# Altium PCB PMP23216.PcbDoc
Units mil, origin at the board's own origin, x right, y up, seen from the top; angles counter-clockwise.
Board outline 1612.03 x 1092.87 mil, 4 copper layers (Top Layer, Signal Layer 1, Signal Layer 2, Bottom Layer), stack 36.024 mil thick; 28 components, 16 nets, 71 pads, 14 vias.
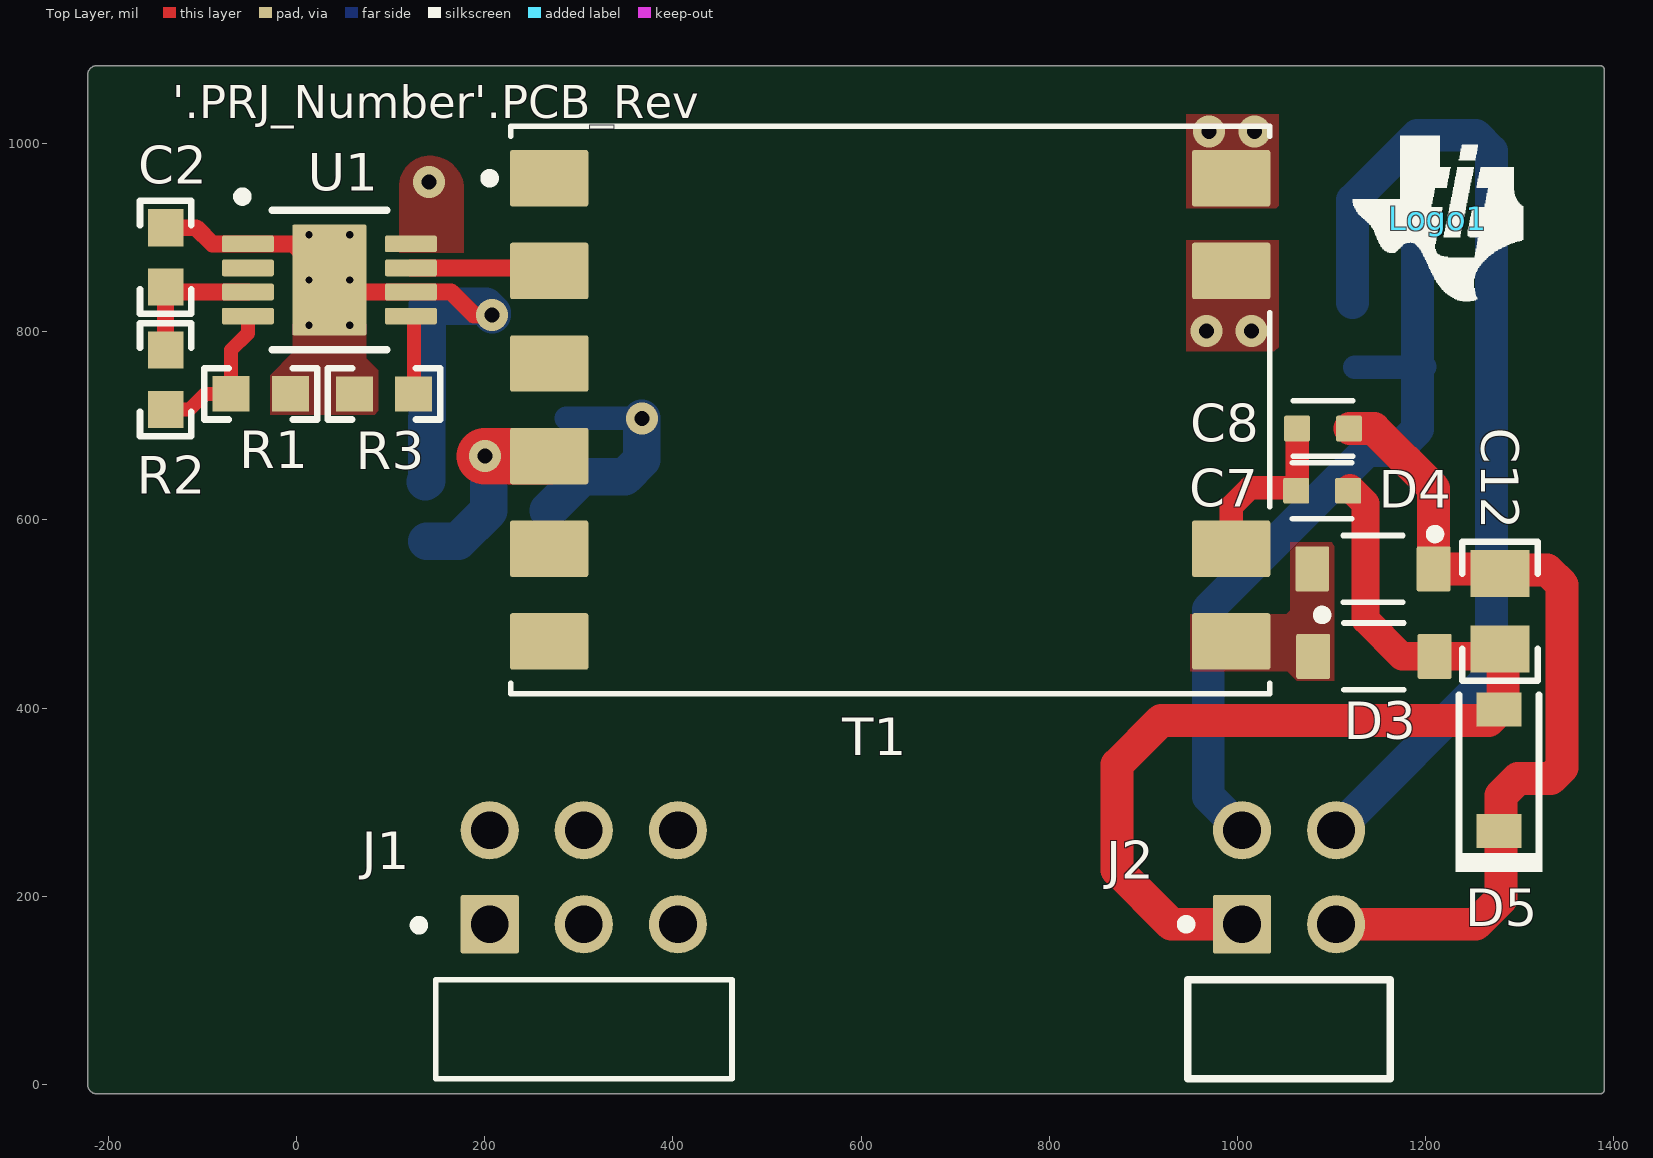
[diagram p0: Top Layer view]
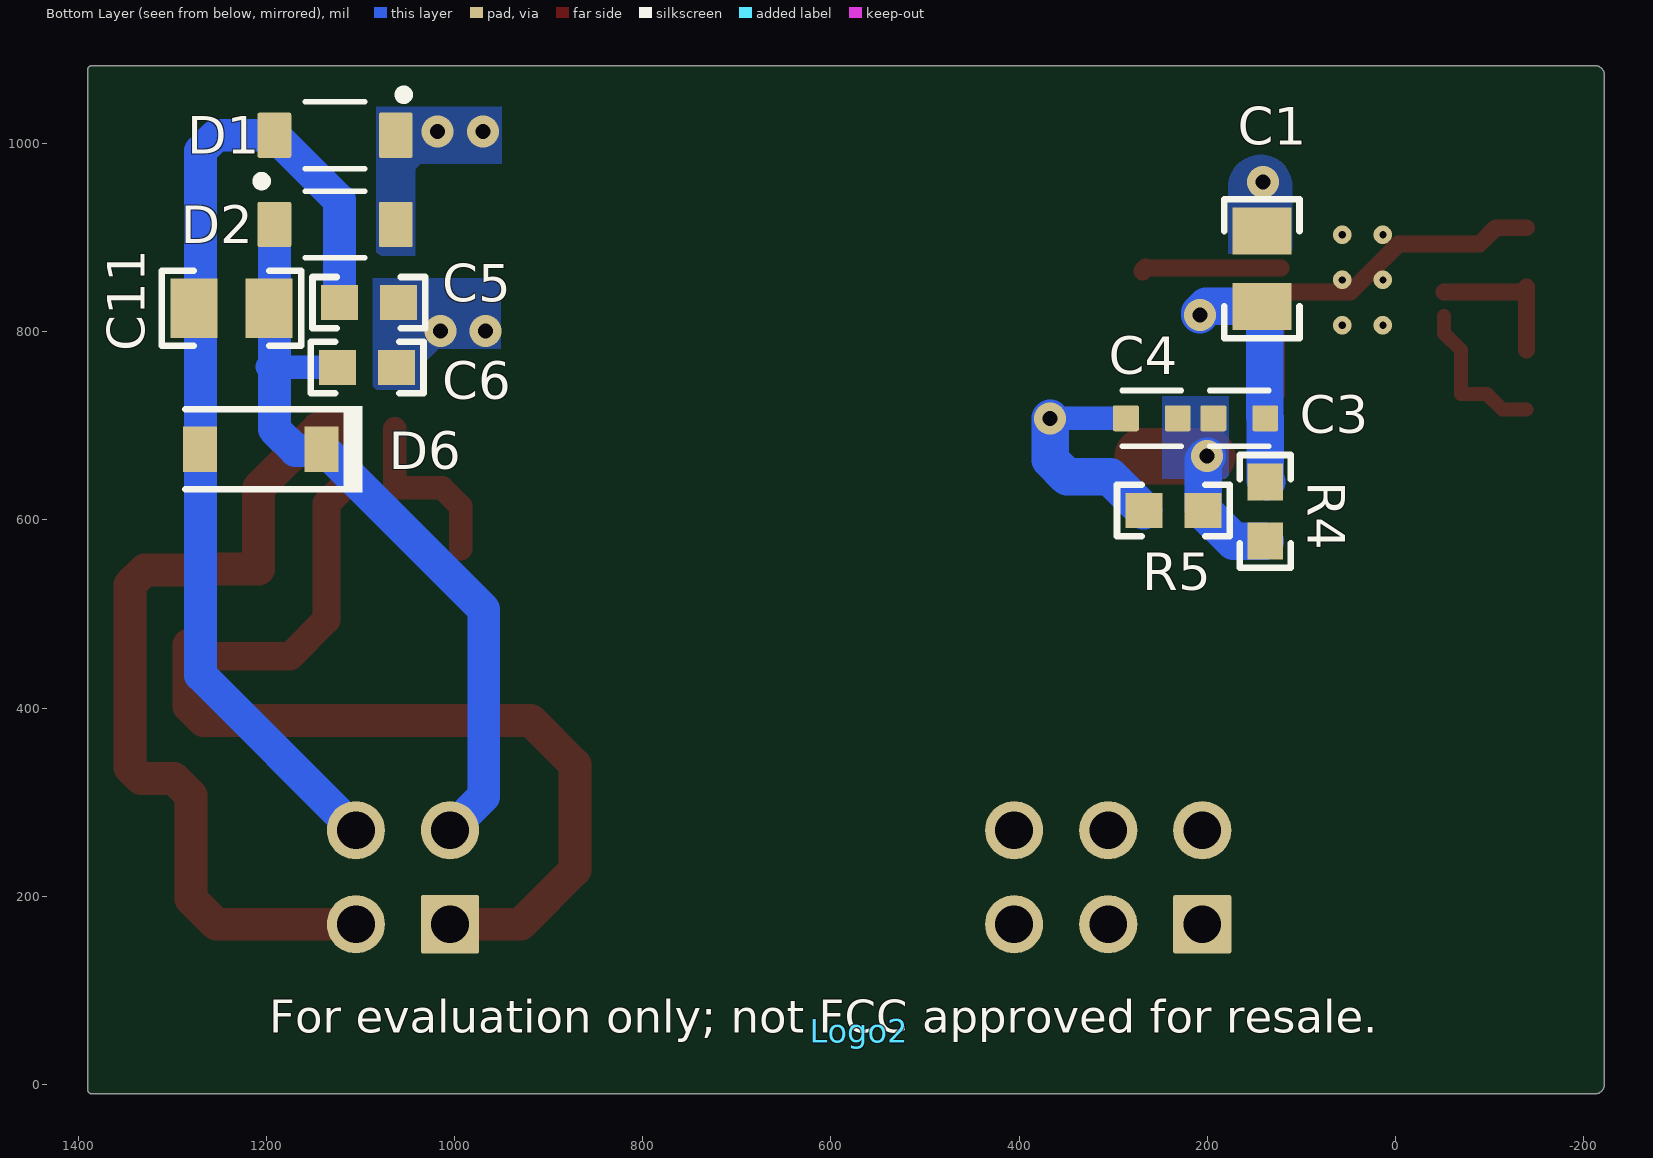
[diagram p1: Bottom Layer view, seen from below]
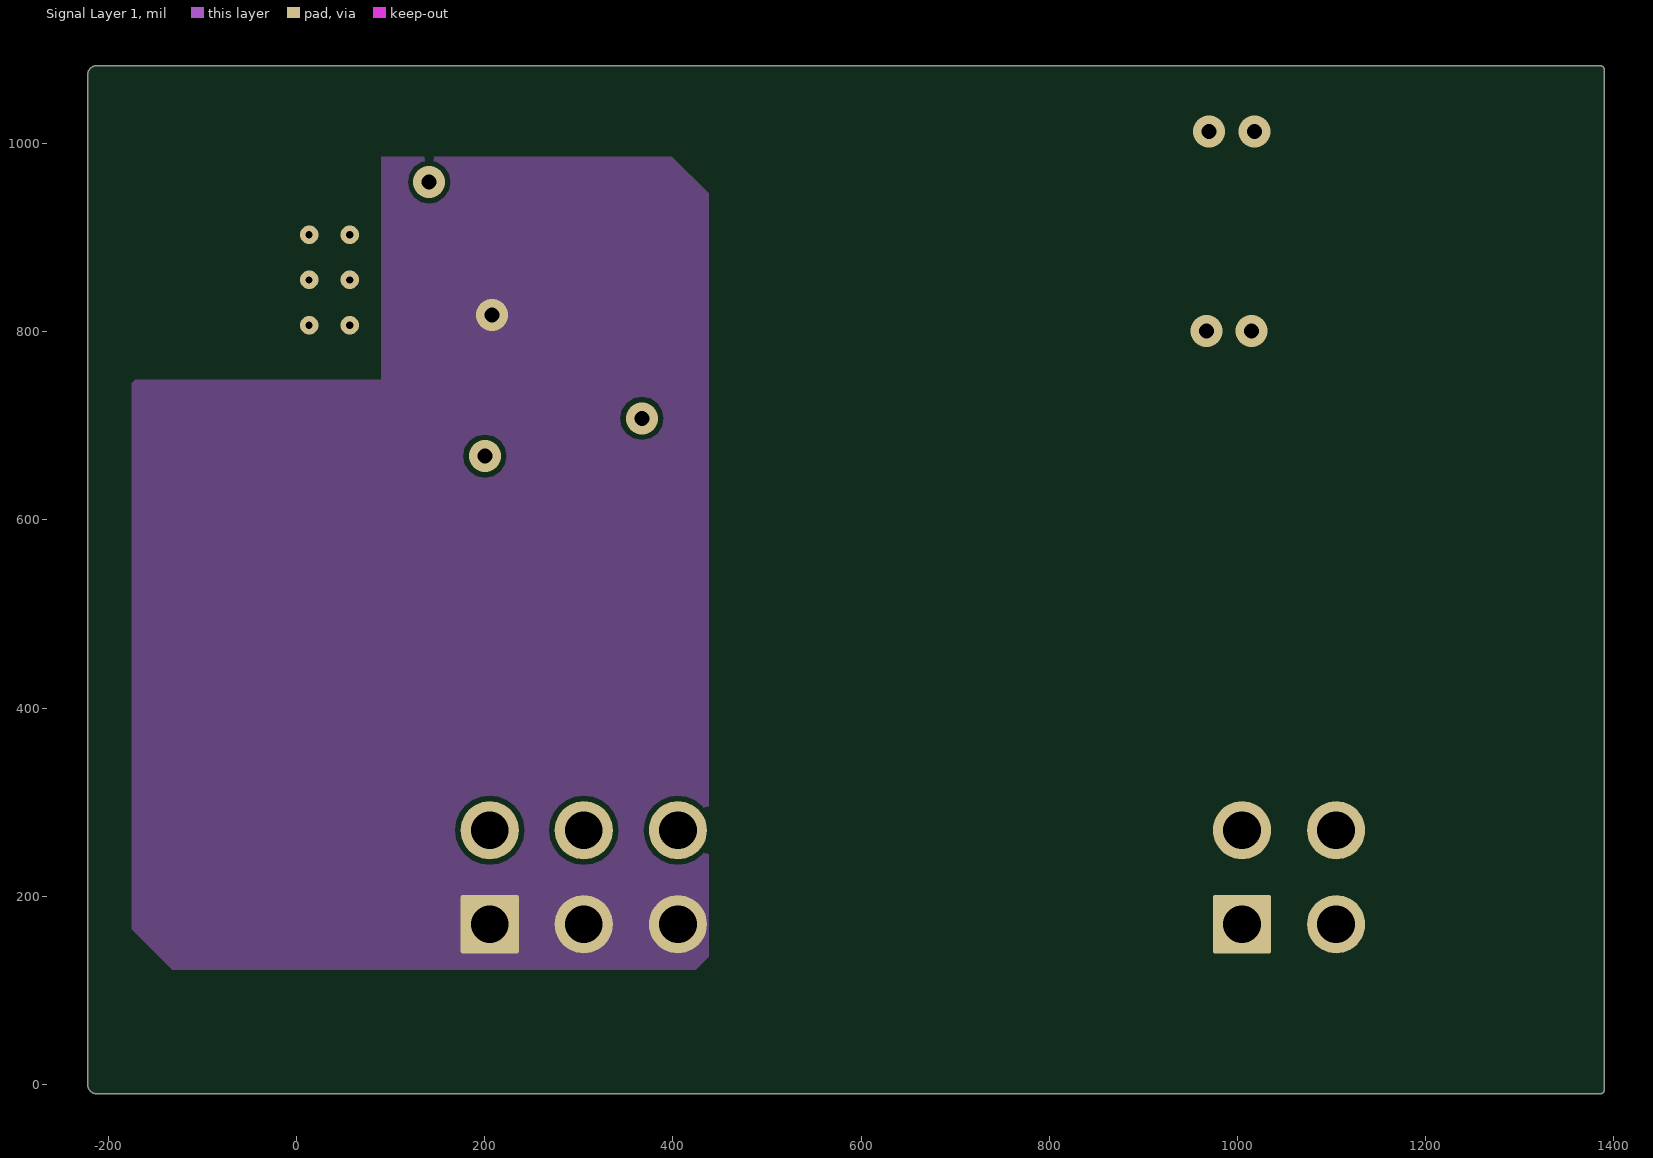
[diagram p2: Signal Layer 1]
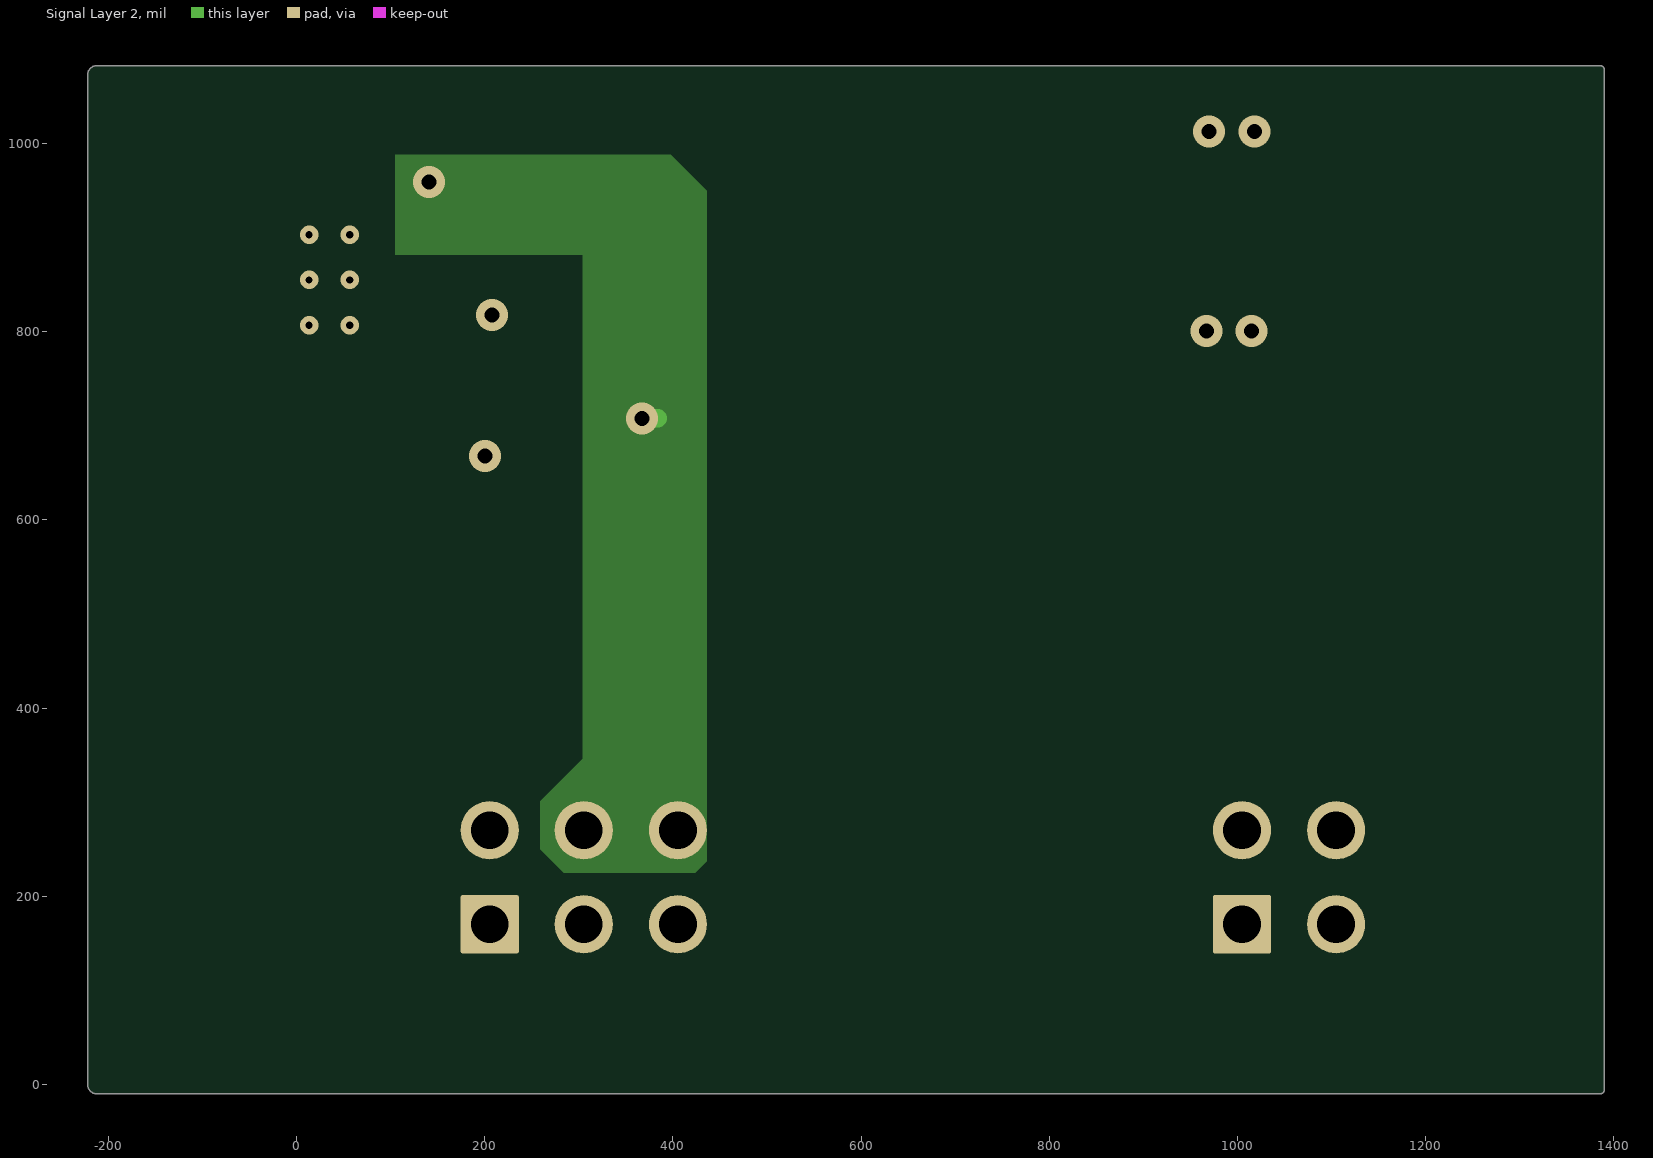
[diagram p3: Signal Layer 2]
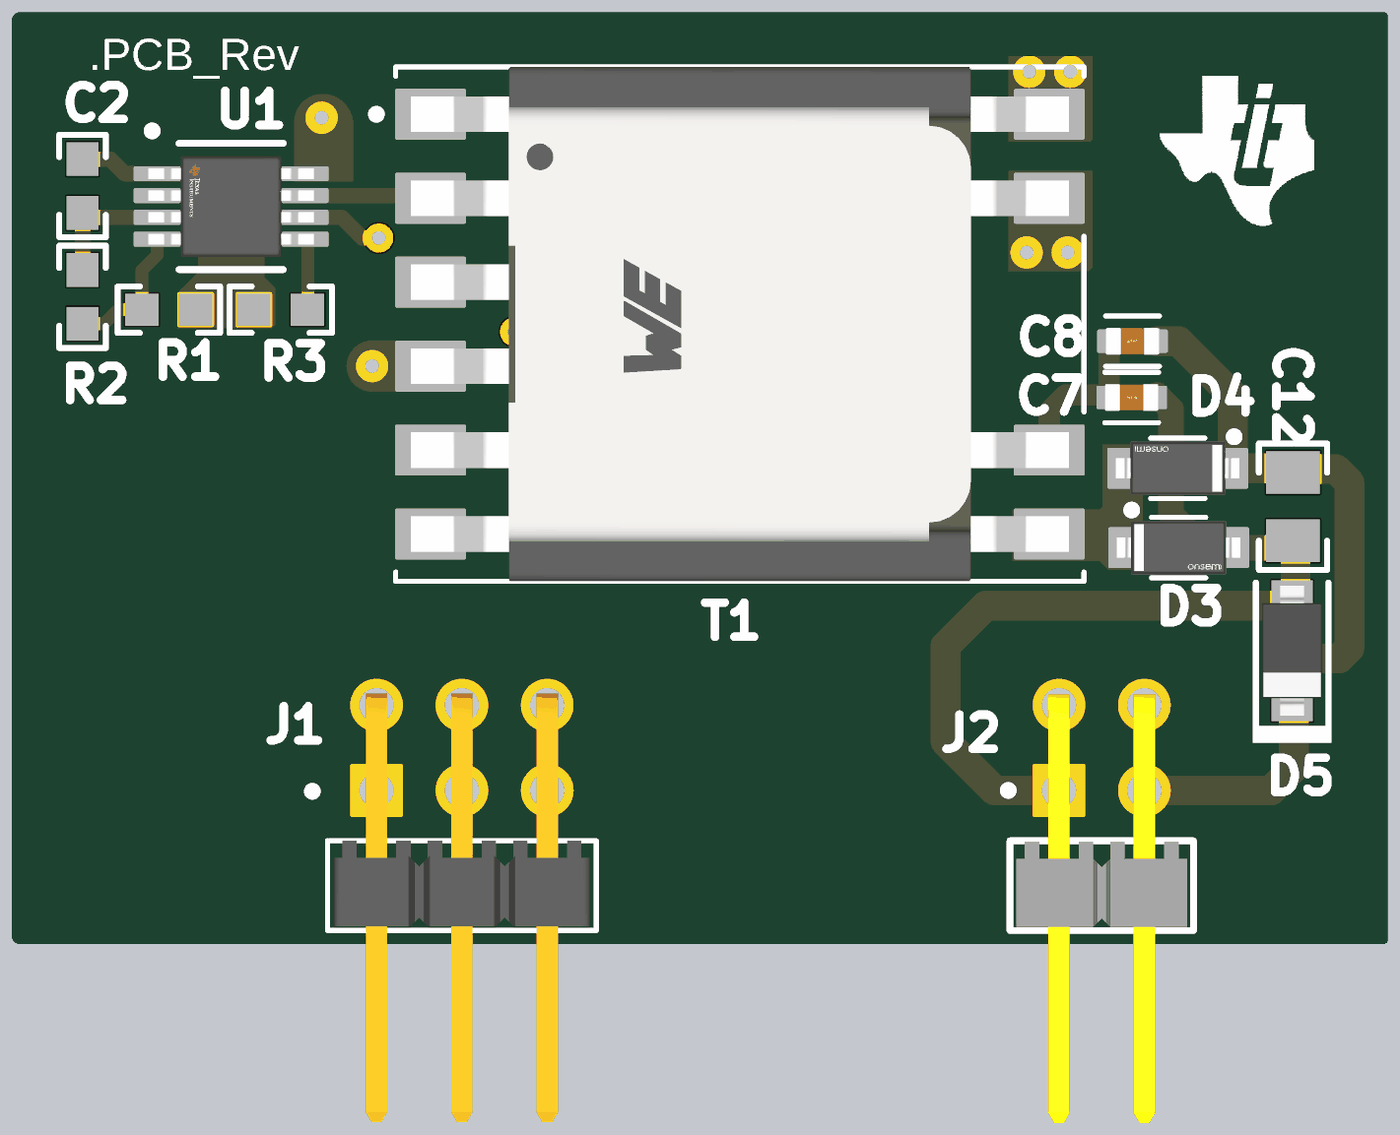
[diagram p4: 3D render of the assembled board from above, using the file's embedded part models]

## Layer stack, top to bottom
Top Solder: solder mask 0.4, Solder Resist, Dk 3.5
Top Layer: signal copper 2.756
Dielectric 2: core 10, FR-4, Dk 4.2
Signal Layer 1: signal copper 2.756
Dielectric1: prepreg 5, FR-4, Dk 4.2
Signal Layer 2: signal copper 2.756
Dielectric 3: core 10, FR-4, Dk 4.2
Bottom Layer: signal copper 2.756
Bottom Solder: solder mask 0.4, Solder Resist, Dk 3.5

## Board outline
-212,-10.02 cw(c-212,0) -222.02,0 -222.02,1072.83 cw(c-212,1072.83) -212,1082.85 1385,1082.85 cw(c1385,1077.84) 1390.01,1077.84 1390.01,-5 cw(c1385,-5) 1385,-10.02

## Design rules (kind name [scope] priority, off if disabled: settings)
AcuteAngle [All] p1: minimum=4.50000000000000E+0001 checktracksonly=FALSE
AssemblyTestPointUsage [All] p1: valid=2
BoardOutlineClearance BoardOutlineClearance_MountingHoles [OnCopper and InComponentClass('Mounting Holes')] p1: gap=39.37 ignorepadtopadclearanceinfootprint=FALSE
BoardOutlineClearance BoardOutlineClearance_Poly [OnCopper and IsPoly] p2: gap=25 ignorepadtopadclearanceinfootprint=FALSE
BoardOutlineClearance [OnCopper and Not InComponentClass('Logo') and not InComponentClass('FiducialMark') and not InRegion(1000,500,4000,800) and not InPoly] p3: gap=25 ignorepadtopadclearanceinfootprint=FALSE
Clearance Clearance_SW_PGND [InNetClass('VSWNET') vs InNetClass('PGND')] p1: gap=50 ignorepadtopadclearanceinfootprint=TRUE
Clearance Clearance_Keepouts [((IsTrack Or IsArc) And Not InPoly) And IsFree and IsKeepOut vs ((IsTrack Or IsArc) And Not InPoly) And IsFree and IsKeepOut] p2: gap=0 ignorepadtopadclearanceinfootprint=FALSE
Clearance Clearance_Poly [InPolygon] p3: gap=5.5 ignorepadtopadclearanceinfootprint=TRUE
Clearance Clearance_FiducialMark [IsKeepOut and InComponentClass('FiducialMark') vs IsPad and InComponentClass('FiducialMark')] p4: gap=0 ignorepadtopadclearanceinfootprint=FALSE
Clearance [All] p5: gap=7 ignorepadtopadclearanceinfootprint=TRUE
ComponentClearance ComponentClearance_MountingHoles_FiducialMarks [InComponentClass('Mounting Holes') vs InComponentClass('FiducialMark')] p1: gap=50 collisioncheckmode=3 verticalgap=10 showdistances=FALSE
ComponentClearance ComponentClearance_Shunt [InComponentClass('Header') vs InComponentClass('Shunt')] p2: gap=0 collisioncheckmode=3 verticalgap=0 showdistances=FALSE
ComponentClearance ComponentClearance_Logo [InComponentClass('Logo')] p3: gap=50 collisioncheckmode=3 verticalgap=10 showdistances=FALSE
ComponentClearance ComponentClearance_ScrewToNut [(HasFootprint('NY PMS 440 0025 PH')) vs (HasFootprint('Keystone_1902C'))] p4: gap=5 collisioncheckmode=3 verticalgap=10 showdistances=FALSE
ComponentClearance ComponentClearance_MountingHoles [InComponentClass('Mounting Holes')] p5: gap=250 collisioncheckmode=3 verticalgap=100000 showdistances=FALSE
ComponentClearance ComponentClearance_SmallPassives [HasFootprint('0201*') or HasFootprint('0402*') or HasFootprint('0508') or HasFootprint('0603*') or HasFootprint('0612') or HasFootprint('0805*') or HasFootprint('0815*') or HasFootprint('0830*') or HasFootprint('1206*') or HasFootprint('1210*') or HasFootprint('1808*') or HasFootprint('1812*') or HasFootprint('1825*') or HasFootprint('2010*') or HasFootprint('2220*') or HasFootprint('2225*') or HasFootprint('2512*') or HasFootprint('2728*') or HasFootprint('3518*') vs HasFootprint('0201*') or HasFootprint('0402*') or HasFootprint('0508') or HasFootprint('0603*') or HasFootprint('0612') or HasFootprint('0805*') or HasFootprint('0815*') or HasFootprint('0830*') or HasFootprint('1206*') or HasFootprint('1210*') or HasFootprint('1808*') or HasFootprint('1812*') or HasFootprint('1825*') or HasFootprint('2010*') or HasFootprint('2220*') or HasFootprint('2225*') or HasFootprint('2512*') or HasFootprint('2728*') or HasFootprint('3518*')] p6: gap=14.96 collisioncheckmode=3 verticalgap=10 showdistances=FALSE
ComponentClearance ComponentClearance_THtoSMT [IsThruComponent vs IsSMTComponent] p7: gap=40 collisioncheckmode=3 verticalgap=30 showdistances=FALSE
ComponentClearance ComponentClearance_THtoTH [IsThruComponent vs IsThruComponent] p8: gap=30 collisioncheckmode=3 verticalgap=30 showdistances=FALSE
ComponentClearance [All] p9: gap=30 collisioncheckmode=3 verticalgap=10 showdistances=FALSE
DiffPairsRouting [All] p1: maxlimit=100 minlimit=10 mostfreqgap=10 toplayer_minwidth=15 toplayer_maxwidth=15 toplayer_prefwidth=15 midlayer1_minwidth=15 midlayer1_maxwidth=15 midlayer1_prefwidth=15 midlayer2_minwidth=15 midlayer2_maxwidth=15 midlayer2_prefwidth=15 bottomlayer_minwidth=15 bottomlayer_maxwidth=15 bottomlayer_prefwidth=15 maxuncoupledlength=1000
FabricationTestPointUsage TestPointUsage [All] p1: valid=2 allowmultiple=FALSE
FabricationTestpoint Testpoint [All] p1: side=3 testpointundercomponent=TRUE minsize=40 maxsize=100 preferedsize=60 minholesize=0 maxholesize=40 preferedholesize=32 testpointgrid=1 allowsidetop=TRUE allowsidebottom=TRUE usegrid=TRUE gridtolerance=0.01
FanoutControl Fanout_LCC [IsLCC] p1: bgadir=Out bgaviamode=Centered fanoutstyle=Auto fanoutdirection=Alternating viagrid=1 // Fanout_LCC (Default Rule)
FanoutControl Fanout_BGA [IsBGA] p2: bgadir=Out bgaviamode=Centered fanoutstyle=Auto fanoutdirection=Alternating viagrid=1 // Fanout_BGA (Default Rule)
FanoutControl Fanout_Default [All] p4: bgadir=Out bgaviamode=Centered fanoutstyle=Auto fanoutdirection=Alternating viagrid=1 // Fanout_Default (Default Rule)
FanoutControl Fanout_Small [(CompPinCount < 5)] p5: bgadir=Out bgaviamode=Centered fanoutstyle=Auto fanoutdirection=OutThenIn viagrid=1 // Fanout_Small (Default Rule)
HoleSize [All] p1: absolutevalues=TRUE maxlimit=251 minlimit=7.87 maxpercent=80.000 minpercent=20.000
MinimumAnnularRing MinimumAnnularRing_ThermalPadVias [IsVia and InAnyComponent] p1: minimumring=5.91
MinimumAnnularRing [All] p2: minimumring=7.87
MinimumSolderMaskSliver MinimumSolderMaskSliver_Logo [InComponentClass('Logo') vs InComponentClass('Logo')] p1: minsoldermaskwidth=0.7
MinimumSolderMaskSliver [All] p2: minsoldermaskwidth=3.94
PlaneConnect [All] p1: planeconnectstyle=Direct reliefexpansion=10 reliefentries=4 reliefconductorwidth=10 reliefairgap=10
PolygonConnect [All] p1: connectstyle=Direct reliefconductorwidth=10 reliefentries=4 polygonreliefangle="90 Angle" airgapwidth=10
RoutingVias ThermalPadVias [IsVia and InAnyComponent] p1: holewidth=7.87 width=19.68 viastyle="Through Hole" minholewidth=7.87 minwidth=19.68 maxholewidth=12.99 maxwidth=23.62
RoutingVias [All] p2: holewidth=16 width=34 viastyle="Through Hole" minholewidth=7.87 minwidth=26 maxholewidth=40 maxwidth=65
SilkToBoardRegionClearance [Not ((IsComment or IsDesignator) And (Hide <> 'False')) and not InRegion(1000,500,4000,800)] p1:
SilkToSilkClearance SilkToSilkClearance_Pb-FreeLogo [(HasFootprint('Pb-Free_Overlay_Medium') OR HasFootprint('Pb-Free_Overlay_Small')) vs (HasFootprint('Pb-Free_Overlay_Medium') OR HasFootprint('Pb-Free_Overlay_Small'))] p1: silktosilkclearance=0
SilkToSilkClearance [All] p2: silktosilkclearance=3.94
SilkToSolderMaskClearance SilkToComponentPadClearance [(IsPad or IsFill or IsRegion) and InAnycomponent] p1: minsilkscreentomaskgap=5 clearancetoexposedcopper=TRUE
SilkToSolderMaskClearance "Silk to Solder Mask Opening" [All] p2: minsilkscreentomaskgap=3.94 clearancetoexposedcopper=FALSE
SolderMaskExpansion [All] p1: expansion=1.97
UnRoutedNet [All] p1: checkbadconnections=TRUE
Width [All] p1: maxlimit=100 minlimit=6 preferedwidth=10 checkconnectedcopper=TRUE
14 further rules are at their usual default settings.

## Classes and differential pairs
net class VSWNET: H_XFMR_BOT H_XFMR_TOP HS_GND ISO_12V_H
net class PGND: ISO_12V_L L_XFMR_BOT L_XFMR_TOP LS_GND
net class INGND: 12V_PRI NetU1_2 OC_DT PGND PRI_BOT RT SW VREG
component class PMP23216_sheet1: C1 C2 C3 C4 C5 C6 C7 C8 C11 C12 D1 D2 D3 D4 D5 D6 J1 J2 R1 R2 R3 R4 R5 T1 U1
component class Logo: Logo1
component class PMP23216_Hardware: Logo1 Logo2 Logo3

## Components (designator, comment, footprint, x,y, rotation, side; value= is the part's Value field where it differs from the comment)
C1 "GRM219R61E106KA12D" 0805_HV 142,867 r270 bottom value=10uF
C2 "GRM185R61A105KE36D" 0603 -139,879 r90 top value=1uF
C3 "C1608X8R1E683M080AA" FP-C1608X8R1E683M080AA_0603-MFG 166,708 r0 bottom value=68nF
C4 "C1608X8R1E683M080AA" FP-C1608X8R1E683M080AA_0603-MFG 259,708 r0 bottom value=68nF
C5 "GRM188R61E475KE11D" 0603 1091,831 r0 bottom value=4.7uF
C6 "GRM188R61E475KE11D" 0603 1093,762 r180 bottom value=4.7uF
C7 "C1608X5R1E475M080AC" FP-C1608X5R1E475M080AC_0603-MFG 1090,631 r180 top value=4.7µF
C8 "C1608X5R1E475M080AC" FP-C1608X5R1E475M080AC_0603-MFG 1091,697 r0 top value=4.7µF
C11 "GRM21BR71E475KA73L" 0805_HV 1237,825 r0 bottom value=4.7uF
C12 "GRM21BR71E475KA73L" 0805_HV 1279,503 r270 top value=4.7uF
D1 "MBR130T3G" FP-MBR130T3G_SOD123-MFG 1127,1008.81 r0 bottom
D2 "MBR130T3G" FP-MBR130T3G_SOD123-MFG 1127,914 r180 bottom
D3 "MBR130T3G" FP-MBR130T3G_SOD123-MFG 1145,455 r0 top
D4 "MBR130T3G" FP-MBR130T3G_SOD123-MFG 1144,548 r180 top
D5 "MMSZ4702T1G" SOD-123 1278,334 r90 top value=15V
D6 "MMSZ4702T1G" SOD-123 1206,675 r0 bottom value=15V
J1 "TSW-103-08-G-D-RA" FP-TSW-103-08-G-D-RA_HDR6-MFG 305.36,61.22 r0 top locked
J2 "TSW-102-08-G-D-RA" FP-TSW-102-08-G-D-RA_HDR4-MFG 1054.87,61.22 r0 top
Logo1 "Texas Instruments" TI_Symbol_Overlay_Small 1213,920 r0 top
Logo2 "FCC disclaimer" FCC_disclaimer 570,57 r180 bottom
Logo3 "WEEE logo" WEEE_Minimum 2670,490 r0 top
R1 "RT0603DRE0711K4L" 0603 -38,734 r180 top value=11.4k
R2 "RT0603BRD073K2L" 0603 -139,749 r90 top value=3.20k
R3 "RT0603DRE0750K5L" 0603 93,733.93 r0 top value=50.5k
R4 "RT0603BRD073K2L" 0603 138.44,609 r270 bottom value=3.20k
R5 "RT0603BRD073K2L" 0603 236,610 r0 bottom value=3.20k
T1 "750320012" FP-750320012_SMT_XFRMR_20MM48_15MM32-MFG 631,717 r0 top locked
U1 "UCC25800DGNRQ1" DGN0008G-MFG 35,855 r0 top

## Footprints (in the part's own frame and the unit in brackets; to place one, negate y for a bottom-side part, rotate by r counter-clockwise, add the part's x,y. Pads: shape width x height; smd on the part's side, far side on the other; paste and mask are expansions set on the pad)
0603 [mm] "0603 from SM-752 data"
  rect 1x0.95 smd: 1(-0.8,0) 2(0.8,0)
  silkscreen extent -1.52,-0.69 1.52,0.69, body extent -0.87,-0.47 0.87,0.47, height 1
0805_HV [mil] "0805 with 30mil clearance between pads"
  rect 50x63 smd: 1(-40,0) 2(40,0)
  silkscreen extent -74,-40 74,40, body extent -43,-29 43,29, height 57
DGN0008G-MFG [mm]
  rrect22% 1.4x0.45 smd paste+0 mask+0: 1(-2.2,0.975) 2(-2.2,0.325) 3(-2.2,-0.325) 4(-2.2,-0.975) 5(2.2,-0.975) 6(2.2,-0.325) 7(2.2,0.325) 8(2.2,0.975)
  rrect5% 2x3 smd paste-1000 mask-1000: 9(0,0)
  silkscreen extent -2.47,-1.88 1.55,2.37, body extent -2.46,-1.5 2.46,1.5, height 1.1
FCC_disclaimer [mil]
FP-750320012_SMT_XFRMR_20MM48_15MM32-MFG [mm]
  rrect7% 2.11x1.52 smd paste+0 mask+0: 1(-9.205,6.25) 2(-9.205,3.75) 3(-9.205,1.25) 4(-9.205,-1.25) 5(-9.205,-3.75) 6(-9.205,-6.25) 7(9.205,-6.25) 8(9.205,-3.75) 9(9.205,3.75) 10(9.205,6.25)
  silkscreen extent -10.94,-7.66 10.24,7.66, body extent -10.36,-7.76 10.36,7.76, height 0.25
FP-C1608X5R1E475M080AC_0603-MFG [mm]
  rrect14% 0.7x0.7 smd paste+0 mask+0: 1(-0.7,0) 2(0.7,0)
  silkscreen extent -0.8,-0.75 0.8,0.75, body extent -1.15,-0.55 1.15,0.55, height 0.25
FP-C1608X8R1E683M080AA_0603-MFG [mm]
  rrect14% 0.7x0.7 smd paste+0 mask+0: 1(-0.7,0) 2(0.7,0)
  silkscreen extent -0.8,-0.75 0.8,0.75, body extent -0.8,-0.4 0.8,0.4, height 0.9
FP-MBR130T3G_SOD123-MFG [mil]
  rrect11% 36x48 smd paste+0 mask+0: 1(-64.5,0) 2(64.5,0)
  silkscreen extent -78,-48 32,35, body extent -72,-31 72,31, height 53
FP-TSW-102-08-G-D-RA_HDR4-MFG [mm]
  rrect6% 1.57x1.57 hole 1.02 paste-1000 mask+0: 1(-1.27,2.77)
  round 1.57 hole 1.02 paste-1000 mask+0: 2(-1.27,5.31) 3(1.27,2.77) 4(1.27,5.31)
  silkscreen extent -2.9,-1.4 2.73,2.89, body extent -2.83,-7.54 2.83,6.2, height 0.25
FP-TSW-103-08-G-D-RA_HDR6-MFG [mm]
  rrect6% 1.57x1.57 hole 1.02 paste-1000 mask+0: 1(-2.54,2.77)
  round 1.57 hole 1.02 paste-1000 mask+0: 2(-2.54,5.31) 3(0,2.77) 4(0,5.31) 5(2.54,2.77) 6(2.54,5.31)
  silkscreen extent -4.57,-1.4 4,2.87, body extent -4.1,-7.54 4.1,6.19, height 0.25
SOD-123 [mm] "On Semi recommended land pattern"
  rect 0.915x1.22 smd: 1(-1.637,0) 2(1.637,0)
  silkscreen extent -2.74,-1.17 2.03,1.17, body extent -1.93,-0.9 1.93,0.9, height 1.35
TI_Symbol_Overlay_Small [mil]
  silkscreen extent -90,-88 91,88
WEEE_Minimum [mil] "WEEElie bin"
  silkscreen extent -95,-172 99,104

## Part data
C1: library part CMP-0008206-2, "CAP, CERM, 10 uF, 25 V, +/- 10%, X5R, 0805", Cap_Case=0805, Manufacturer=MuRata, Supplier Part Number 1=490-7207-1-ND, TempCo=X5R, Tolerance_%=10%, Value1=Unknown, Value2=25V, ValueDisplayed=10uF
C2: library part CMP-0007156-4, "CAP, CERM, 1 uF, 10 V, +/- 10%, X5R, 0603", Cap_Case=0603, Manufacturer=MuRata, Supplier Part Number 1=490-3893-1-ND, TempCo=X5R, Tolerance_%=10%, Value1=Unknown, Value2=10V, ValueDisplayed=1uF
C3 C4: library part CMP-0094554-1, "Multilayer Ceramic Capacitors 68nF ±20% 25V X8R SMD 0603", Manufacturer=TDK, Operating Temperature Range="-55°C to +150°C", TempCo=0.15, Temperature Characteristic=X8R, Tolerance_%=0.2%, ValueDisplayed=68nF, Voltage=50V
C5 C6: library part CMP-0007347-4, "CAP, CERM, 4.7 uF, 25 V, +/- 10%, X5R, 0603", Cap_Case=0603, Manufacturer=MuRata, Supplier Part Number 1=490-7203-1-ND, TempCo=X5R, Tolerance_%=10%, Value1=Unknown, Value2=25V, ValueDisplayed=1µF
C7 C8: library part CMP-0094553-1, "Multilayer Ceramic Capacitors 4.7µF ±20% 25V X5R SMD 0603", Manufacturer=TDK, Operating Temperature Range="-55°C to +85°C", TempCo=0.15, Temperature Characteristic=X5R, Tolerance_%=0.2%, ValueDisplayed=1µF, Voltage=50V
C11 C12: library part CMP-0008346-2, "CAP, CERM, 4.7 uF, 25 V, +/- 10%, X7R, 0805", Cap_Case=0805, Manufacturer=MuRata, Supplier Part Number 1=490-9962-1-ND, TempCo=X7R, Tolerance_%=10%, Value1=Unknown, Value2=25V, ValueDisplayed=4.7uF
D1 D2 D3 D4: library part CMP-0094495-1, "Diode Schottky 30 V 1A Surface Mount SOD-123", Digikey Part Number=MBR130T3GOSCT-ND, Forward Current=1A, Manufacturer=onsemi, Max Surge Forward Current=5.5A, Mouser Part Number=863-MBR130T3G, Operating Temperature Range="-65°C to +125°C", Peak Reverse Current=60uA
D5 D6: library part CMP-0005745-1, "Diode, Zener, 15 V, 500 mW, SOD-123", Manufacturer="ON Semiconductor", Power_W=500mW, Supplier Part Number 1=MMSZ4702T1GOSCT-ND, Value1=0.5W
J1: library part CMP-0090622-1, "Connector Header Through Hole, Right Angle 6 position 0.100\" (2.54mm)", Current_A=5.7A, Digikey Part Number=SAM1037-03-ND, Manufacturer=Samtec, Mouser Part Number=200-TSW10308GDRA, Operating Temperature Range="-55°C to +125°C", Voltage_V=550V
J2: library part CMP-0088304-1, "CONN HEADER R/A 4POS 2.54MM", Digikey Part Number=SAM1037-02-ND, Manufacturer=Samtec, Mouser Part Number=200-TSW10208GDRA, Operating Temperature Range="-55°C to +125°C"
Logo1: library part CMP-0074838-1, "Texas Instrument Corporate Signature"
Logo2: library part CMP-0074847-1, "FCC_disclaimer"
Logo3: library part CMP-0074769-1
R1: library part CMP-0024611-1, "RES, 11.4 k, 0.5%, 0.1 W, 0603", Manufacturer="Yageo America", Power_W=100mW, TempCo="50 ppm/C", Tolerance_%=0.5%, Value2=0.1W, Value_Code=11k4, ValueDisplayed=11.4k
R2: library part CMP-0024193-2, "RES, 3.20 k, 0.1%, 0.1 W, 0603", Manufacturer="Yageo America", Power_W=100mW, TempCo="25 ppm/C", Tolerance_%=0.1%, Value2=0.1W, Value_Code=3k20, ValueDisplayed=3.20k
R3: library part CMP-0025375-2, "RES, 50.5 k, 0.5%, 0.1 W, 0603", Manufacturer="Yageo America", Power_W=100mW, TempCo="50 ppm/C", Tolerance_%=0.5%, Value2=0.1W, Value_Code=50k5, ValueDisplayed=50.5k
R4 R5: library part CMP-0024193-2, "RES, 3.20 k, 0.1%, 0.1 W, 0603", Manufacturer="Yageo America", Power_W=100mW, TempCo="25 ppm/C", Tolerance_%=0.1%, Value2=0.1W, Value_Code=3k20, ValueDisplayed=100k
T1: library part CMP-0094840-1, "Transformer, 1:1.11:1.11, 0.065Ohm PRI, 0.07Ohm SEC, 141uH, 5000VAC, 20.48x15.32x10.16mm, SMT", Manufacturer="Wurth Electronics", Operating Temperature Range="-40°C to +125°C", Voltage_Isolation_Vrms=5kV
U1: library part CMP-0088494-2, "Open Loop LLC Transformer Driver for Isolated Bias Supplies", Manufacturer="Texas Instruments", Max Supply Voltage=36V, Min Supply Voltage=12V, Nominal Supply Current=500uA, Operating Temperature Range="-40°C to +150°C", Switching Frequency=100-2000kHz

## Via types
v1: diameter 34, hole 16, Top Layer to Bottom Layer, 8 vias
v2: diameter 19.68, hole 7.87, Top Layer to Bottom Layer, 6 vias

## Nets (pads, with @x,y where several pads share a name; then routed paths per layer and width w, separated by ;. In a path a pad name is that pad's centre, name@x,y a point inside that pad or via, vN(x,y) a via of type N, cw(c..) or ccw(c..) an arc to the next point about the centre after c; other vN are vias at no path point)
5V_PRI: J1.2
12V_PRI: C1.1 C4.2 J1.4 J1.6 R5.2 U1.8 | length 263.3
  Signal Layer 2 w20: v1(367,708) 384,708
  Bottom Layer w25: C4.2 v1(367,708)
  Bottom Layer w40: R5.2 303.5,646 349,646 367,664 v1(367,708)
  other v1: 141,959
H_XFMR_BOT: D3.1 D4.2 T1.7
H_XFMR_TOP: C7.2 C8.1 T1.8 | length 186.2
  Top Layer w25: T1.8 993.4,614.4 1013,634 1063.44,634 C8.1
HS_GND: C7.1 C12.2 D3.2 D5.2 J2.1 | length 1083.4
  Top Layer w30: C7.1@1119.56,634 1136,617.56 1136,494 1175,455 D3.2 1270,455 C12.2@1282,467
  Top Layer w35: J2.1 929.72,170.28 872,228 872,340 919,387 1267,387 1282,402 C12.2@1282,467
ISO_12V_H: C8.2 C12.1 D4.1 D5.1 J2.3 | length 911.9
  Top Layer w35: J2.3 1253.28,170.28 1280,197 1280,307 1298,325 1333,325 1345,337 1345,531 1329,547 1282,547 1281,548 D4.1 1208.5,633.5 1145,697 C8.2@1119.56,697
ISO_12V_L: C6.1 C11.1 D2.1 D6.1 J2.2 | length 858.5
  Bottom Layer w25: J2.2 J2.2@1004.87,282.13 ; C6.1 1191.5,762 1198,762 1199,763 ; D2.1 D2.1@1193.5,912
  Bottom Layer w35: J2.2 969,306.14 969,505 1138,674 1169,674 1191.5,696.5 1191.5,762 D2.1
L_XFMR_BOT: D1.1 D2.2 T1.10
  other v1: 970,1013 1018,1013
L_XFMR_TOP: C5.1 C6.2 T1.9
  other v1: 967,801 1015,801
LS_GND: C5.2 C11.2 D1.2 D6.2 J2.4 | length 1082
  Bottom Layer w35: J2.4 1270,435.41 1270,992 1253.19,1008.81 D1.2 1122.5,939.81 C5.2
OC_DT: R1.2 R2.1 U1.4 | length 166.4
  Top Layer w15: R2.1 -113.5,717.5 -97,734 R1.2 -69.5,780.5 -51.61,798.39 U1.4
PGND: C1.2 C2.2 C3.1 J1.1 J1.3 J1.5 R1.1 R3.1 R4.1 U1.1 U1.6 U1.9 | length 643.3
  Top Layer w18: C2.2 -106.5,910.5 -89.39,893.39 U1.1 -3.39,893.39 U1.9 47.8,842.2 U1.6 164.44,842.2 188.65,818 v1(208,818)
  Bottom Layer w40: R4.1@137,640.5 138.44,641.94 C3.1 ; C3.1@139,709 C1.2@139,828 ; C1.2 201,827 208,820 v1(208,818)
  other v2: 13.35,806.97 56.65,806.97 13.35,855 56.65,855 13.35,903.03 56.65,903.03
PRI_BOT: C3.2 C4.1 R4.2 R5.1 T1.4 | length 207.5
  Top Layer w60: v1(200.21,667.79) T1.4
  Bottom Layer w40: R4.2 172.01,577.5 R5.1 204.5,663.5 v1(200.21,667.79)
RT: R3.2 U1.5 | length 85
  Top Layer w15: U1.5 124.99,813.24 R3.2@124.99,733
SW: T1.2 U1.7 | length 148.3
  Top Layer w18: U1.7 T1.2@265.44,867.8
  Top Layer w20: T1.2@265.44,867.8 T1.2
VREG: C2.1 R2.2 U1.3 | length 156.6
  Top Layer w18: R2.2 C2.1 -133.7,842.2 U1.3
pads on no net: T1.1 T1.3 T1.5 T1.6 U1.2

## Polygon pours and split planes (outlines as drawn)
H_XFMR_BOT on Top Layer "Top Layer-H_XFMR_BOT" (solid, pour order 68): 950,439 1053,439 1063,429 1103,429 1103,575 1101,577 1100,576 1056,576 1056,504 1052,500 950,500
L_XFMR_TOP on Top Layer "Top Layer-L_XFMR_TOP 1" (solid, pour order 60): 945.78,897 945.78,779 1039.28,779 1044,783.72 1044,897
L_XFMR_BOT on Top Layer "Top Layer-L_XFMR_BOT" (solid, pour order 56): 945.78,1031 945.78,931 1041,931 1044,934 1044,1031
12V_PRI on Top Layer "Top Layer-12V_PRI" (solid, pour order 52): 109,884 109,954 cw(c142,954) 142,987 cw(c142,951) 178,951 178,884
PGND on Top Layer "Top Layer-PGND" (solid, pour order 50): -4,808 -4,778 -28,754 -28,712 83,712 84,713 87,713 87,759 74,772 74,808
L_XFMR_BOT on Bottom Layer "Bottom Layer-L_XFMR_BOT" (solid, pour order 58): 950,1039 950,978.62 1035.83,978.62 1042,972.45 1042,880.62 1080,880.62 1082,878.62 1083,879.62 1083,1039
12V_PRI on Bottom Layer "Bottom Layer-12V_PRI" (solid, pour order 54): 111,884 110,885 110,955 cw(c143,955) 143,988 cw(c143,953) 178,953 178,883 111.87,883 111,882.13
L_XFMR_TOP on Bottom Layer "Bottom Layer-L_XFMR_TOP" (solid, pour order 18): 951,857 951,782.08 1016.79,782.07 1031,767.86 1031,738.39 1087,738.39 1087,857
PRI_BOT on Bottom Layer "Bottom Layer-PRI_BOT" (solid, pour order 36): 177,655.09 177,644 248,644 248,731.41 177,731.41
no net on Bottom Layer "Bottom Layer-No Net" (solid, pour order 6): 338.65,872.61
PGND on Signal Layer 1 "Signal Layer 1-PGND" (solid, pour order 10): 90,749 90,986 399.01,986 438,947.01 438,135.85 424.15,122 -131.99,122 -174.93,164.92 -175.11,749
12V_PRI on Signal Layer 2 "Signal Layer 2-12V_PRI" (solid, pour order 42): 304,346 259,301 259,250 284,225 290,225 424,225 436,237 436,950 398,988 105,988 105,882 304,882

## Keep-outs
Keep-Out Layer:
  text ".Layer_Name" at 577,-858.49 h60

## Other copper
Top Layer:
  text ".Layer_Name" at 577,-858.49 h60
Bottom Layer:
  text ".Layer_Name" at 577,-858.49 h60

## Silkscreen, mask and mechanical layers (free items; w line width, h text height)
Top Overlay:
  text "'.PRJ_Number'.PCB_Rev" at -132,1015 h60
  text ".Layer_Name" at 577,-858.49 h60
Bottom Overlay:
  text ".Layer_Name" at 577,-858.49 h60
Top Paste:
  text ".Layer_Name" at 577,-858.49 h60
Bottom Paste:
  text ".Layer_Name" at 577,-858.49 h60
Top Solder:
  text ".Layer_Name" at 577,-858.49 h60
  text ".Layer_Name" at 577,-858.49 h60
Bottom Solder:
  text ".Layer_Name" at 577,-858.49 h60
Drill Guide:
  text ".Layer_Name" at 577,-858.49 h60
M1 Board Outline:
  lines w10: -217,0 ccw(c-212,0) -212,-5 ; -217,0 ccw(c-212,0) -212,-5 ; -217,0 -217,1072.83 ; -217,1072.83 cw(c-212,1072.83) -212,1077.84 ; -217,1072.83 cw(c-212,1072.83) -212,1077.84 ; -212,-5 1385,-5 1385,1077.84 -212,1077.84
  text ".Layer_Name" at 577,-858.49 h60
M2 Board Dimensions:
  rectangle: 0,-275 125,-150
  rectangle: 125,-400 500,-275
  lines w7: 0,-275 1000,-275 ; 125,-400 125,-150 ; 250,-400 250,-150 ; 500,-400 500,-150 ; 750,-400 750,-150 ; 0,-400 1000,-400 1000,-150 0,-150 0,-400
  text ".Layer_Name" at 577,-858.49 h60
M3 3D STEP Top:
  text ".Layer_Name" at 577,-858.49 h60
M4 3D STEP Bottom:
  text ".Layer_Name" at 577,-858.49 h60
M5 Assembly Top:
  lines w10: -292,-930.17 6308,-930.17 ; -292,-726.83 6310,-726.83 ; -292,-523.5 -292,-1133.5 3713,-1133.5 6310,-1133.5 6310,-523.5 -291.5,-523.5 -291.5,-1133.5 1284,-1133.5 ; 2173,-1133.5 2173,-523.5 ; 3440,-726.83 3440,-523.5 ; 4280,-726.83 4280,-523.5 ; 4902,-1140 4902,-937.17
  text "COMPONENTS MARKED 'DNP' SHOULD NOT BE POPULATED." at 1153.5,-318.5 h60
  text "ASSEMBLY VARIANT:" at 1153,-434 h60
  text ".VariantName" at 2189,-434 h60
  text "PCB VIEWED FROM TOP SIDE" at -228.5,-655.67 h60
  text "BOARD #:" at 2248,-655.67 h60
  text ".PRJ_Number" at 2793.5,-655.67 h60
  text "REV:" at 3638,-655.67 h60
  text ".PCB_Rev" at 3929.5,-655.67 h60
  text "SVN REV:" at 4476,-655.67 h60
  text ".VersionControl_RevNumber" at 4982,-655.67 h60
  text "TID #:" at 2248,-859 h60
  text ".TID" at 2793.5,-859 h60
  text "PLOT NAME =" at -228.5,-1064.34 h60
  text ".plot_File_Name" at 577,-1064.34 h60
  text "GENERATED    :" at 2250,-1064.34 h60
  text ".Print_Date" at 3119.5,-1064.34 h60
  text ".Print_Time" at 3848.5,-1064.34 h60
  text "TEXAS INSTRUMENTS" at 5113,-1064.34 h60
M6 Assembly Bottom:
  lines w10: -292.5,-727.33 6309.5,-727.33 ; -290.5,-930.67 6309.5,-930.67 ; 1115.5,-1140.5 1115.5,-937.67 ; 1737.5,-727.33 1737.5,-524 ; 2577.5,-727.33 2577.5,-524 ; 3844.5,-1134 3844.5,-524 ; 4733.5,-1134 6309,-1134 6309,-524 -292.5,-524 -292.5,-1134 2304.5,-1134 6309.5,-1134 6309.5,-524
  text "COMPONENTS MARKED 'DNP' SHOULD NOT BE POPULATED." at 6102,-318 h60
  text ".VariantName" at 5058,-434 h60
  text "ASSEMBLY VARIANT:" at 6097,-434 h60
  text ".VersionControl_RevNumber" at 1035.5,-656.17 h60
  text "SVN REV:" at 1541.5,-656.17 h60
  text ".PCB_Rev" at 2088,-656.17 h60
  text "REV:" at 2379.5,-656.17 h60
  text ".PRJ_Number" at 3224,-656.17 h60
  text "BOARD #:" at 3769.5,-656.17 h60
  text "PCB VIEWED FROM BOTTOM SIDE" at 6246,-656.17 h60
  text ".TID" at 3224,-859.5 h60
  text "TID #:" at 3769.5,-859.5 h60
  text "TEXAS INSTRUMENTS" at 904.5,-1064.84 h60
  text ".Print_Time" at 2169,-1064.84 h60
  text ".Print_Date" at 2898,-1064.84 h60
  text "GENERATED    :" at 3767.5,-1064.84 h60
  text ".plot_File_Name" at 5440.5,-1064.84 h60
  text "PLOT NAME =" at 6246,-1064.84 h60
M9 Title Sheet:
  drawing of 57 lines, arcs and shapes, not listed
  text "1" at 739.84,8036.5 h70
  text "2" at 3235.5,8036.5 h70
  text "3" at 5724.84,8036.5 h70
  text "4" at 8231.51,8036.5 h70
  text "5" at 10730.5,8036.5 h70
  text "6" at 13235.5,8036.5 h70
  text "A" at -416.5,6893.5 h70
  text "A" at 14383.5,6893.5 h70
  text "B" at -416.5,4513.5 h70
  text "B" at 14383.5,4513.5 h70
  text "C" at -416.5,2138.5 h70
  text "C" at 14383.5,2138.5 h70
  text "PROJECT TITLE:" at 11343.5,277.5 h45
  text ".PRJ_Title" at 11393.5,144.17 h70
  text "DESIGNED FOR:" at 11343.5,-23.5 h45
  text ".PRJ_Customer" at 11393.5,-163.5 h70
  text "D" at -416.5,-231.5 h70
  text "D" at 14383.5,-231.5 h70
  text "FILE NAME:" at 11343.5,-323.5 h45
  text ".PCB_File_Name_No_Path" at 11393.5,-443.5 h70
  text "Texas Instruments (TI) and/or its licensors do not warrant the accuracy or completeness of this specification" at 6374,-605.34 h45
  text "ENGINEER:" at 11343.5,-613.5 h45
  text "LAYOUT BY:" at 12848.5,-613.5 h45
  text "or any information contained therein. TI and/or its licensors do not warrant that this design will meet" at 6329.01,-718 h45
  text ".PRJ_Engineer" at 11393.5,-768.49 h70
  text ".PCB_Layout" at 12899,-768.49 h70
  text "the specifications, will be suitable for your application or fit for any particular purpose, or will operate in" at 6329.01,-830.67 h45
  text ".Layer_Name" at 577,-858.49 h60
  text "ALTIUM DESIGNER VERSION:" at 12848.5,-923.5 h45
  text "an implementation. TI and/or its licensors do not warrant that the design is production worthy. You should" at 6329.01,-943.33 h45
  text "completely validate and test your design implementation to confirm the system functionality for your application." at 6374,-1056 h45
  text ".print_Scale" at 11393.5,-1056.83 h70
  text ".Application_BuildNumber" at 12899,-1056.83 h70
  text "1" at 739.84,-1263.5 h70
  text "2" at 3235.5,-1263.5 h70
  text "3" at 5724.84,-1263.5 h70
  text "4" at 8231.51,-1263.5 h70
  text "5" at 10730.5,-1263.5 h70
  text "6" at 13235.5,-1263.5 h70
M10 Fab Notes:
  drawing of 189 lines, arcs and shapes, not listed
  text "DESIGN INFORMATION" at 12382.02,6356.17 h60
  text "MIN. TRACK WIDTH:" at 11737.46,6224.05 h60
  text "8" at 12833.7,6224.05 h60
  text "MIL" at 12988.46,6224.05 h60
  text "7.874" at 12667.32,6102.36 h60
  text "MIN. CLEARANCE:" at 11737.46,6099.92 h60
  text "MIL" at 12988.46,6099.92 h60
  text "MIN. VIA PAD SIZE:" at 11737.46,5975.8 h60
  text "24" at 12803.71,5975.8 h60
  text "MIL" at 12988.46,5975.8 h60
  text "0.05mm (2MIL)" at 12432.46,5845.9 h60
  text "MINIMUM ANNULAR RING" at 11408.23,5837.67 h60
  text "EXTERNAL" at 13140.46,5837.67 h60
  text "PER" at 11608.23,5727.55 h60
  text "IPC-D-275 CLASS 2 LEVEL C" at 11828.23,5727.54 h60
  text "MIL, HOLES" at 13316.46,5627.07 h60
  text "+/-" at 12924,5618.48 h60
  text "+/-" at 13778,5618.48 h60
  text "REGISTRATION TOLERANCES:" at 11408.23,5617.42 h60
  text "METAL" at 12608,5617.42 h60
  text "5" at 13184.2,5617.42 h60
  text "3" at 14017.2,5617.42 h60
  text "MIL" at 14133.46,5617.42 h60
  text "HOLE SIZE TOLERANCE (UNLESS OTHERWISE SPECIFIED):" at 11408.23,5519.1 h60
  text "+/-" at 13778,5516.23 h60
  text "3" at 14017.2,5515.17 h60
  text "MIL" at 14133.46,5515.17 h60
  text "MATERIAL:" at 11333.46,5377.52 h60
  text "FR-4 High Tg" at 12319.9,5249 h60
  text "X" at 12175.46,5241.01 h60
  text "FR-408" at 11754.46,5236.49 h60
  text "OTHER" at 13242.46,5236.49 h60
  text "62 MIL (1.6mm) +/-10%" at 12074.56,5093.46 h60
  text "X" at 11954.46,5091.01 h60
  text "THICKNESS:" at 11408.23,5085.24 h60
  text "OTHER" at 13359.46,5085.24 h60
  text "TOLERANCE:" at 11408.23,4946.92 h60
  text "X" at 12256.46,4946.92 h60
  text "ANSI IPC-6012 TYPE 3 CLASS 2" at 12434.48,4946.92 h60
  text "OTHER +/-" at 12434.46,4802.73 h60
  text "BOW & TWIST:" at 11408.23,4657.54 h60
  text "X" at 12256.46,4657.54 h60
  text "ANSI IPC-6012 TYPE 3 CLASS 2" at 12434.48,4657.54 h60
  text "OTHER +/-" at 12434.46,4510.85 h60
  text "DRILLING:" at 11333.46,4380.23 h60
  text "NC_DRILL FILES" at 13094.46,4275.04 h60
  text "REFERENCE:" at 11408.23,4271.1 h60
  text "X" at 12065.46,4271.01 h60
  text "AS SHOWN" at 12243.46,4271.1 h60
  text "X" at 12966.46,4271.1 h60
  text "OTHER" at 13392.46,4128.85 h60
  text "PTH COPPER THICKNESS:" at 11407.91,4125.32 h60
  text "X" at 12547.14,4125.32 h60
  text "20-30 um" at 12675.14,4125.32 h60
  text "BOARD FINISH:" at 11333.46,3977.73 h60
  text "SILKSCREEN:" at 11488.68,3867.6 h60
  text "X" at 12446.46,3867.6 h60
  text "TOP" at 12563.46,3867.6 h60
  text "X" at 12956.46,3867.6 h60
  text "BOTTOM" at 13074.46,3867.6 h60
  text "SILKSCREEN COLOR:" at 11488.68,3712.41 h60
  text "X" at 12445.46,3712.41 h60
  text "WHITE" at 12563.46,3712.41 h60
  text "OTHER" at 13074.46,3712.41 h60
  text "X" at 12576.46,3568.96 h60
  text "GREEN" at 12694.46,3568.96 h60
  text "OTHER" at 13312.46,3568.96 h60
  text "SOLDER RESIST COLOR:" at 11488.68,3562.1 h60
  text "X" at 12576.46,3414.71 h60
  text "MATTE" at 12694.46,3414.71 h60
  text "SEMI-GLOSS" at 13312,3414.07 h60
  text "IMMERSION GOLD (ENIG)" at 12394.46,3241.94 h60
  text "ENEPIG" at 13732,3234.72 h60
  text "SURFACE FINISH:" at 11333.46,3233.72 h60
  text "IMM. TIN/SILVER OR EQUIV" at 11663,3096.4 h60
  text "X" at 12918.99,3095.92 h60
  text "OTHER" at 13094.46,3092.47 h60
  text "ARRAY/PANEL:" at 11333.46,2937.09 h60
  text "CUT AND TRIM PER M1 BOARD OUTLINE" at 12394.46,2928.87 h60
  text "N.C. ROUTE" at 12394.46,2792.9 h60
  text "X" at 13082.46,2792.9 h60
  text "V. SCORE" at 13260.46,2792.9 h60
  text "CERTIFICATION:" at 11333.46,2663.77 h60
  text "MATERIALS AND WORKMANSHIP FOR ALL PCBS" at 12058.46,2663.77 h60
  text "TO MEET OR EXCEED THE REQUIREMENTS OF:" at 12058.46,2569.71 h60
  text "X" at 11695.97,2441.08 h60
  text "ANSI IPC-A-600F CLASS ->" at 11823.96,2441.08 h60
  text "X" at 13471.97,2441.08 h60
  text "2" at 13581.96,2441.08 h60
  text "1" at 13266.96,2439.58 h60
  text "3" at 13935.96,2439.58 h60
  text "X" at 12507.97,2293.39 h60
  text "RoHS" at 12635.96,2293.39 h60
  text "OTHER" at 13280.36,2293.39 h60
  text "PER ORDER" at 13677.42,2293.39 h60
  text "ALL BOARDS MUST MEET OR EXCEED UL94-V0 REQUIREMENTS." at 11361,2139.57 h60
  text "PCB MUST BEAR THE UL94V-0 UL REGISTERED MATERIAL ID NUMBER" at 11361,2023.5 h60
  text "ADDITIONAL REQUIREMENTS:" at 11333.46,1854.08 h60
  text "MICROSECTION:" at 11408.23,1746.95 h60
  text "YES" at 12313.96,1746.95 h60
  text "REQUIRED" at 13175.46,1602.62 h60
  text "BARE BOARD ELEC. TEST:" at 11408.23,1599.76 h60
  text "X" at 12591.1,1599.76 h60
  text "NONE" at 12713.96,1599.76 h60
  text "PER ORDER" at 13767.46,1599.76 h60
  text "XX MIL VIAS REQUIRE NON-CONDUCTIVE FILL AND PLANARIZE" at 11576.38,1394.82 h59
  text "XX MIL VIAS REQUIRE CONDUCTIVE FILL AND PLANARIZE" at 11584.38,1290.84 h60
  text "OUTER XX MIL TRACES REQUIRE 50 OHM SINGLE-ENDED IMPEDANCE" at 11583.39,1127.46 h58
  text "LAYER 2 & 3 (INNER LAYERS) XX MIL WIDE, XX MIL SPACE / TRACES REQUIRE 100 OHM DIFFERENTIAL IMPEDANCE" at 11575.39,891.74 h60
  text ".Layer_Name" at 577,-858.49 h60
M11 Gerber Information:
  lines w10: -292,-930.17 6308,-930.17 ; -292,-726.83 6310,-726.83 ; -292,-523.5 -292,-1133.5 3713,-1133.5 6310,-1133.5 6310,-523.5 -291.5,-523.5 -291.5,-1133.5 1284,-1133.5 ; 2173,-1133.5 2173,-523.5 ; 3440,-726.83 3440,-523.5 ; 4280,-726.83 4280,-523.5 ; 4902,-1140 4902,-937.17
  text "ALL ARTWORK VIEWED FROM TOP SIDE" at -228.5,-655.67 h60
  text "BOARD #:" at 2248,-655.67 h60
  text ".PRJ_Number" at 2793.5,-655.67 h60
  text "REV:" at 3638,-655.67 h60
  text ".PCB_Rev" at 3929.5,-655.67 h60
  text "SVN REV:" at 4476,-655.67 h60
  text ".VersionControl_RevNumber" at 4982,-655.67 h60
  text "LAYER NAME =" at -228.5,-858.49 h60
  text "TID #:" at 2248,-859 h60
  text ".TID" at 2793.5,-859 h60
  text "PLOT NAME =" at -228.5,-1064.34 h60
  text ".plot_File_Name" at 577,-1064.34 h60
  text "GENERATED    :" at 2250,-1064.34 h60
  text ".Print_Date" at 3119.5,-1064.34 h60
  text ".Print_Time" at 3848.5,-1064.34 h60
  text "TEXAS INSTRUMENTS" at 5113,-1064.34 h60
M12 Stackup:
  drawing of 295 lines, arcs and shapes, not listed
  text "Layer" at 6579.95,6330.24 h60
  text "Name" at 6989.86,6330.24 h60
  text "Material" at 7929.6,6330.24 h60
  text "Thickness" at 8789.37,6330.24 h60
  text "Constant" at 9439.21,6330.24 h60
  text "Board Layer Stack" at 10009.07,6330.24 h60
  text "1" at 6579.95,6210.24 h60
  text "Top Overlay" at 6989.86,6210.24 h60
  text "2" at 6579.95,6090.24 h60
  text "Top Solder" at 6989.86,6090.24 h60
  text "Solder Resist" at 7929.6,6090.24 h60
  text "0.40mil" at 8789.37,6090.24 h60
  text "3.5" at 9439.21,6090.24 h60
  text "3" at 6579.95,5970.24 h60
  text "Top Layer" at 6989.86,5970.24 h60
  text "Copper" at 7929.6,5970.24 h60
  text "2.76mil" at 8789.37,5970.24 h60
  text "4" at 6579.95,5850.24 h60
  text "Dielectric 2" at 6989.86,5850.24 h60
  text "FR-4" at 7929.6,5850.24 h60
  text "10.00mil" at 8789.37,5850.24 h60
  text "4.2" at 9439.21,5850.24 h60
  text "5" at 6579.95,5730.24 h60
  text "Signal Layer 1" at 6989.86,5730.24 h60
  text "Copper" at 7929.6,5730.24 h60
  text "2.76mil" at 8789.37,5730.24 h60
  text "6" at 6579.95,5610.24 h60
  text "Dielectric1" at 6989.86,5610.24 h60
  text "FR-4" at 7929.6,5610.24 h60
  text "5.00mil" at 8789.37,5610.24 h60
  text "4.2" at 9439.21,5610.24 h60
  text "7" at 6579.95,5490.24 h60
  text "Signal Layer 2" at 6989.86,5490.24 h60
  text "Copper" at 7929.6,5490.24 h60
  text "2.76mil" at 8789.37,5490.24 h60
  text "8" at 6579.95,5370.24 h60
  text "Dielectric 3" at 6989.86,5370.24 h60
  text "FR-4" at 7929.6,5370.24 h60
  text "10.00mil" at 8789.37,5370.24 h60
  text "4.2" at 9439.21,5370.24 h60
  text "9" at 6579.95,5250.24 h60
  text "Bottom Layer" at 6989.86,5250.24 h60
  text "Copper" at 7929.6,5250.24 h60
  text "2.76mil" at 8789.37,5250.24 h60
  text "10" at 6579.95,5130.24 h60
  text "Bottom Solder" at 6989.86,5130.24 h60
  text "Solder Resist" at 7929.6,5130.24 h60
  text "0.40mil" at 8789.37,5130.24 h60
  text "3.5" at 9439.21,5130.24 h60
  text "11" at 6579.95,5010.24 h60
  text "Bottom Overlay" at 6989.86,5010.24 h60
  text ".Layer_Name" at 577,-858.49 h60
M13 Component Bodies Top:
  text ".Layer_Name" at 577,-858.49 h60
M14 Component Bodies Bottom:
  text ".Layer_Name" at 577,-858.49 h60
M15 Courtyards Top:
  text ".Layer_Name" at 577,-858.49 h60
M16 Courtyards Bottom:
  text ".Layer_Name" at 577,-858.49 h60
Drill Drawing:
  circle w10: c476.76,2464.44 r33.33
  lines w10: 443.43,2281.1 510.09,2281.1 510.09,2347.77 443.43,2347.77 443.43,2281.1 ; 443.43,2647.77 510.09,2647.77 476.76,2581.1 443.43,2647.77
  lines w15: 383.64,2236.1 10854.74,2236.1 ; 383.64,2686.1 10854.74,2686.1 ; 934.51,2086.1 934.51,2836.1 ; 1474.37,2086.1 1474.37,2836.1 ; 2564.06,2086.1 2564.06,2836.1 ; 3069.93,2086.1 3069.93,2836.1 ; 3803.73,2086.1 3803.73,2836.1 ; 5303.28,2086.1 5303.28,2836.1 ; 5893.13,2086.1 5893.13,2836.1 ; 6638.93,2086.1 6638.93,2836.1 ; 7288.76,2086.1 7288.76,2836.1 ; 8142.52,2086.1 8142.52,2836.1 ; 9476.13,2086.1 9476.13,2836.1 ; 383.64,2086.1 10854.74,2086.1 10854.74,2836.1 383.64,2836.1 383.64,2086.1
  text "Symbol" at 473.64,2731.1 h72
  text "Count" at 979.51,2731.1 h72
  text "Hole Size" at 1519.37,2731.1 h72
  text "Plated" at 2609.06,2731.1 h72
  text "Hole Type" at 3114.93,2731.1 h72
  text "Drill Layer Pair" at 3848.73,2731.1 h72
  text "Via/Pad" at 5348.28,2731.1 h72
  text "Pad Shape" at 5938.13,2731.1 h72
  text "Template" at 6683.93,2731.1 h72
  text "Description" at 7333.76,2731.1 h72
  text "Hole Tolerance (+)" at 8187.52,2731.1 h72
  text "Hole Tolerance (-)" at 9521.13,2731.1 h72
  text "6" at 979.51,2581.1 h60
  text "0.200mm (7.87mil)" at 1519.37,2581.1 h60
  text "PTH" at 2609.06,2581.1 h60
  text "Round" at 3114.93,2581.1 h60
  text "Top Layer - Bottom Layer" at 3848.73,2581.1 h60
  text "Via" at 5348.28,2581.1 h60
  text "Rounded" at 5938.13,2581.1 h60
  text "v50h20m50" at 6683.93,2581.1 h60
  text "8" at 979.51,2431.1 h60
  text "0.406mm (16.00mil)" at 1519.37,2431.1 h60
  text "PTH" at 2609.06,2431.1 h60
  text "Round" at 3114.93,2431.1 h60
  text "Top Layer - Bottom Layer" at 3848.73,2431.1 h60
  text "Via" at 5348.28,2431.1 h60
  text "Rounded" at 5938.13,2431.1 h60
  text "v86h41" at 6683.93,2431.1 h60
  text "10" at 979.51,2281.1 h60
  text "1.020mm (40.16mil)" at 1519.37,2281.1 h60
  text "PTH" at 2609.06,2281.1 h60
  text "Round" at 3114.93,2281.1 h60
  text "Top Layer - Bottom Layer" at 3848.73,2281.1 h60
  text "Pad" at 5348.28,2281.1 h60
  text "(Mixed)" at 5938.13,2281.1 h60
  text "(Mixed)" at 6683.93,2281.1 h60
  text "24 Total" at 979.51,2131.1 h60
  text ".Layer_Name" at 577,-858.49 h60
M17 Embedded Cavity:
  text ".Layer_Name" at 577,-858.49 h60
M18 Embedded Assembly:
  text ".Layer_Name" at 577,-858.49 h60
M19 Embedded Keepout:
  text ".Layer_Name" at 577,-858.49 h60

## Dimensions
0,-400 to 1000,-400 on M2 Board Dimensions
0,0 to -212,1082.85 on M2 Board Dimensions
0,0 to -222.02,0 on M2 Board Dimensions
